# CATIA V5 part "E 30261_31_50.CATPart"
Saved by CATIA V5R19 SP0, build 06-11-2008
Definition: E 30261_31_50
Nomenclature: E 30261_31_50
Description: PART--DESC
Material "Steel": density 7860 kg/m3, Young's modulus 2e+11 Pa, Poisson ratio 0.266, thermal expansion 1.17e-05 1/K
Bounding box of the stored display mesh (mm): x -45 to 20, y -25 to 25, z -31 to 26
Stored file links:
  G:\UTB\Kombinované\Bakalářská práce\Catia\FORMA\E 30261_31_50.CATPart
  D:\Aplikace\CATIA\Nová složka\win_b64\startup\materials\Catalog.CATMaterial
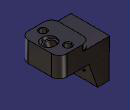
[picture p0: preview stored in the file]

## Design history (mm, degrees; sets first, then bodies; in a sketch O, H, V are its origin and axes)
Body1 "E 30261_31_50" (main body)
  Solid1: solid without history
